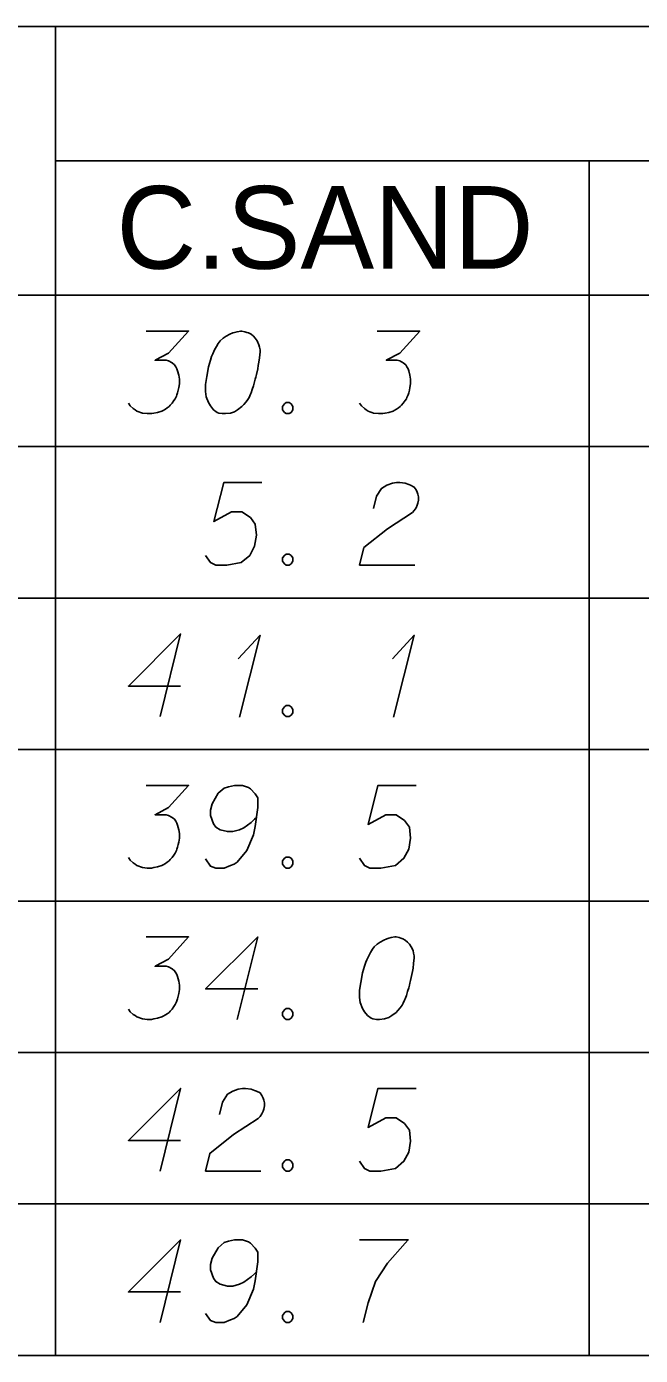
# Model space of a CAD drawing. Extents: x 2074207 to 2076812, y 516372 to 523312.
# Drawn here: x 2076524.4 to 2076560.1, y 517302 to 517379.2 of the extents above; entities that cross this region are included whole.
import ezdxf

# ---------------------------------------------------------------- set-up
doc = ezdxf.new("R2010")
doc.units = 0
for name, color, linetype in [('Prop DirtTable_ Soil Test Results - Outline (Major)', 7, 'Continuous'), ('Prop DirtTable_ Soil Test Results - Outline (Minor)', 7, 'Continuous'), ('Prop DirtTable_ Soil Test Results - Tx (Header - Small)', 7, 'Continuous'), ('Prop DirtTable_ Soil Test Results - Tx (Sample Data)', 7, 'Continuous')]:
    doc.layers.add(name, color=color, linetype=linetype)

msp = doc.modelspace()

# ---------------------------------------------------------------- linework, layer by layer
at = {"layer": 'Prop DirtTable_ Soil Test Results - Outline (Major)'}
for p, q in [((2076260.609, 517363.585), (2076811.903, 517363.585)), ((2076260.609, 517363.585), (2076811.903, 517363.585)), ((2076260.609, 517301.985), (2076811.903, 517301.985))]:
    msp.add_line(p, q, dxfattribs=at)
at = {"layer": 'Prop DirtTable_ Soil Test Results - Outline (Minor)'}
for p, q in [((2076260.609, 517379.185), (2076811.903, 517379.185)), ((2076526.074, 517379.185), (2076526.074, 517354.785)), ((2076526.074, 517371.385), (2076731.93, 517371.385)), ((2076557.094, 517371.385), (2076557.094, 517354.785)), ((2076260.609, 517354.785), (2076811.903, 517354.785)), ((2076260.609, 517354.785), (2076811.903, 517354.785)), ((2076526.074, 517354.785), (2076526.074, 517345.985)), ((2076557.094, 517354.785), (2076557.094, 517345.985)), ((2076260.609, 517345.985), (2076811.903, 517345.985)), ((2076260.609, 517345.985), (2076811.903, 517345.985)), ((2076526.074, 517345.985), (2076526.074, 517337.185)), ((2076557.094, 517345.985), (2076557.094, 517337.185)), ((2076260.609, 517337.185), (2076811.903, 517337.185)), ((2076260.609, 517337.185), (2076811.903, 517337.185)), ((2076526.074, 517337.185), (2076526.074, 517328.385)), ((2076557.094, 517337.185), (2076557.094, 517328.385)), ((2076260.609, 517328.385), (2076811.903, 517328.385)), ((2076260.609, 517328.385), (2076811.903, 517328.385)), ((2076526.074, 517328.385), (2076526.074, 517319.585)), ((2076557.094, 517328.385), (2076557.094, 517319.585)), ((2076260.609, 517319.585), (2076811.903, 517319.585)), ((2076260.609, 517319.585), (2076811.903, 517319.585)), ((2076526.074, 517319.585), (2076526.074, 517310.785)), ((2076557.094, 517319.585), (2076557.094, 517310.785)), ((2076260.609, 517310.785), (2076811.903, 517310.785)), ((2076260.609, 517310.785), (2076811.903, 517310.785)), ((2076526.074, 517310.785), (2076526.074, 517301.985)), ((2076557.094, 517310.785), (2076557.094, 517301.985)), ((2076260.609, 517301.985), (2076811.903, 517301.985))]:
    msp.add_line(p, q, dxfattribs=at)
at = {"layer": 'Prop DirtTable_ Soil Test Results - Tx (Sample Data)'}
for points in [[(2076531.339, 517361.498), (2076533.808, 517361.498), (2076532.644, 517360.213), (2076531.868, 517359.797), (2076532.503, 517359.797), (2076532.644, 517359.759), (2076532.714, 517359.722), (2076532.785, 517359.684), (2076532.855, 517359.646), (2076532.997, 517359.533), (2076533.067, 517359.419), (2076533.138, 517359.306), (2076533.173, 517359.192), (2076533.243, 517358.928), (2076533.279, 517358.701), (2076533.279, 517358.588), (2076533.279, 517358.437), (2076533.243, 517358.21), (2076533.208, 517358.059), (2076533.173, 517357.907), (2076533.138, 517357.794), (2076533.102, 517357.718), (2076533.067, 517357.643), (2076533.032, 517357.567), (2076532.961, 517357.454), (2076532.855, 517357.303), (2076532.75, 517357.189), (2076532.679, 517357.114), (2076532.573, 517357.038), (2076532.467, 517356.963), (2076532.326, 517356.887), (2076532.256, 517356.849), (2076532.009, 517356.774), (2076531.797, 517356.736), (2076531.656, 517356.698), (2076531.409, 517356.698), (2076531.127, 517356.736), (2076531.021, 517356.774), (2076530.915, 517356.811), (2076530.809, 517356.849), (2076530.704, 517356.925), (2076530.598, 517357), (2076530.421, 517357.152), (2076530.316, 517357.303)], [(2076536.912, 517361.498), (2076536.842, 517361.498), (2076536.63, 517361.46), (2076536.489, 517361.422), (2076536.383, 517361.385), (2076536.207, 517361.309), (2076535.995, 517361.196), (2076535.819, 517361.082), (2076535.642, 517360.931), (2076535.536, 517360.78), (2076535.431, 517360.591), (2076535.325, 517360.402), (2076535.219, 517360.175), (2076535.148, 517360.024), (2076535.078, 517359.797), (2076534.972, 517359.419), (2076534.866, 517358.852), (2076534.796, 517358.399), (2076534.796, 517357.983), (2076534.831, 517357.681), (2076534.972, 517357.341), (2076535.078, 517357.152), (2076535.254, 517356.925), (2076535.466, 517356.774), (2076535.572, 517356.736), (2076535.783, 517356.698), (2076535.96, 517356.698), (2076536.242, 517356.736), (2076536.489, 517356.811), (2076536.665, 517356.925), (2076536.912, 517357.114), (2076537.018, 517357.227), (2076537.159, 517357.378), (2076537.265, 517357.529), (2076537.335, 517357.643), (2076537.406, 517357.832), (2076537.441, 517357.907), (2076537.512, 517358.096), (2076537.582, 517358.323), (2076537.653, 517358.55), (2076537.688, 517358.701), (2076537.723, 517358.815), (2076537.759, 517358.966), (2076537.829, 517359.306), (2076537.865, 517359.495), (2076537.9, 517359.684), (2076537.935, 517359.948), (2076537.97, 517360.289), (2076537.97, 517360.402), (2076537.935, 517360.553), (2076537.9, 517360.704), (2076537.794, 517360.931), (2076537.688, 517361.082), (2076537.582, 517361.196), (2076537.441, 517361.309), (2076537.3, 517361.385), (2076537.194, 517361.422), (2076537.089, 517361.46), (2076536.912, 517361.498)], [(2076544.779, 517361.498), (2076547.248, 517361.498), (2076546.084, 517360.213), (2076545.308, 517359.797), (2076545.943, 517359.797), (2076546.084, 517359.759), (2076546.154, 517359.722), (2076546.225, 517359.684), (2076546.295, 517359.646), (2076546.437, 517359.533), (2076546.507, 517359.419), (2076546.578, 517359.306), (2076546.613, 517359.192), (2076546.683, 517358.928), (2076546.719, 517358.701), (2076546.719, 517358.588), (2076546.719, 517358.437), (2076546.683, 517358.21), (2076546.648, 517358.059), (2076546.613, 517357.907), (2076546.578, 517357.794), (2076546.542, 517357.718), (2076546.507, 517357.643), (2076546.472, 517357.567), (2076546.401, 517357.454), (2076546.295, 517357.303), (2076546.19, 517357.189), (2076546.119, 517357.114), (2076546.013, 517357.038), (2076545.907, 517356.963), (2076545.766, 517356.887), (2076545.696, 517356.849), (2076545.449, 517356.774), (2076545.237, 517356.736), (2076545.096, 517356.698), (2076544.849, 517356.698), (2076544.567, 517356.736), (2076544.461, 517356.774), (2076544.355, 517356.811), (2076544.249, 517356.849), (2076544.144, 517356.925), (2076544.038, 517357), (2076543.861, 517357.152), (2076543.756, 517357.303)], [(2076539.487, 517357.341), (2076539.664, 517357.341), (2076539.769, 517357.265), (2076539.875, 517357.114), (2076539.875, 517356.925), (2076539.769, 517356.774), (2076539.664, 517356.698), (2076539.487, 517356.698), (2076539.381, 517356.774), (2076539.276, 517356.925), (2076539.276, 517357.114), (2076539.381, 517357.265), (2076539.487, 517357.341)], [(2076538.076, 517352.698), (2076535.854, 517352.698), (2076535.289, 517350.43), (2076536.312, 517350.997), (2076536.912, 517350.997), (2076537.406, 517350.657), (2076537.688, 517350.279), (2076537.759, 517349.637), (2076537.653, 517348.994), (2076537.371, 517348.465), (2076536.877, 517348.049), (2076536.03, 517347.898), (2076535.395, 517347.898), (2076535.078, 517348.049), (2076534.796, 517348.465)], [(2076544.567, 517351.186), (2076544.743, 517351.904), (2076545.026, 517352.358), (2076545.343, 517352.547), (2076545.66, 517352.66), (2076545.907, 517352.698), (2076546.084, 517352.698), (2076546.401, 517352.66), (2076546.613, 517352.585), (2076546.719, 517352.547), (2076546.93, 517352.433), (2076547.036, 517352.282), (2076547.107, 517352.131), (2076547.142, 517352.018), (2076547.177, 517351.867), (2076547.177, 517351.678), (2076547.142, 517351.489), (2076547.107, 517351.375), (2076547.036, 517351.224), (2076546.93, 517351.073), (2076546.825, 517350.959), (2076545.378, 517350.015), (2076544.003, 517348.918), (2076543.756, 517347.898), (2076546.966, 517347.898)], [(2076539.487, 517348.541), (2076539.664, 517348.541), (2076539.769, 517348.465), (2076539.875, 517348.314), (2076539.875, 517348.125), (2076539.769, 517347.974), (2076539.664, 517347.898), (2076539.487, 517347.898), (2076539.381, 517347.974), (2076539.276, 517348.125), (2076539.276, 517348.314), (2076539.381, 517348.465), (2076539.487, 517348.541)], [(2076533.349, 517340.874), (2076530.316, 517340.874), (2076533.349, 517343.898), (2076532.15, 517339.098)], [(2076536.7, 517342.462), (2076537.97, 517343.822), (2076536.771, 517339.06)], [(2076545.66, 517342.462), (2076546.93, 517343.822), (2076545.731, 517339.06)], [(2076539.487, 517339.741), (2076539.664, 517339.741), (2076539.769, 517339.665), (2076539.875, 517339.514), (2076539.875, 517339.325), (2076539.769, 517339.174), (2076539.664, 517339.098), (2076539.487, 517339.098), (2076539.381, 517339.174), (2076539.276, 517339.325), (2076539.276, 517339.514), (2076539.381, 517339.665), (2076539.487, 517339.741)], [(2076531.339, 517335.098), (2076533.808, 517335.098), (2076532.644, 517333.813), (2076531.868, 517333.397), (2076532.503, 517333.397), (2076532.644, 517333.359), (2076532.714, 517333.322), (2076532.785, 517333.284), (2076532.855, 517333.246), (2076532.997, 517333.133), (2076533.067, 517333.019), (2076533.138, 517332.906), (2076533.173, 517332.792), (2076533.243, 517332.528), (2076533.279, 517332.301), (2076533.279, 517332.188), (2076533.279, 517332.037), (2076533.243, 517331.81), (2076533.208, 517331.659), (2076533.173, 517331.507), (2076533.138, 517331.394), (2076533.102, 517331.318), (2076533.067, 517331.243), (2076533.032, 517331.167), (2076532.961, 517331.054), (2076532.855, 517330.903), (2076532.75, 517330.789), (2076532.679, 517330.714), (2076532.573, 517330.638), (2076532.467, 517330.563), (2076532.326, 517330.487), (2076532.256, 517330.449), (2076532.009, 517330.374), (2076531.797, 517330.336), (2076531.656, 517330.298), (2076531.409, 517330.298), (2076531.127, 517330.336), (2076531.021, 517330.374), (2076530.915, 517330.411), (2076530.809, 517330.449), (2076530.704, 517330.525), (2076530.598, 517330.6), (2076530.421, 517330.752), (2076530.316, 517330.903)], [(2076534.796, 517330.827), (2076535.078, 517330.411), (2076535.395, 517330.298), (2076535.889, 517330.298), (2076536.242, 517330.449), (2076536.454, 517330.525), (2076536.63, 517330.638), (2076537.194, 517331.318), (2076537.582, 517332.226), (2076537.688, 517332.717), (2076537.829, 517333.813), (2076537.829, 517334.38), (2076537.688, 517334.607), (2076537.406, 517334.909), (2076537.3, 517334.985), (2076536.947, 517335.098), (2076536.489, 517335.098), (2076536.136, 517335.022), (2076535.889, 517334.947), (2076535.536, 517334.644), (2076535.184, 517334.04), (2076535.078, 517333.662), (2076535.078, 517333.359), (2076535.254, 517332.868), (2076535.395, 517332.679), (2076535.642, 517332.528), (2076536.066, 517332.415), (2076536.383, 517332.415), (2076536.771, 517332.528), (2076537.018, 517332.641), (2076537.441, 517332.944), (2076537.653, 517333.133), (2076537.759, 517333.246)], [(2076547.036, 517335.098), (2076544.814, 517335.098), (2076544.249, 517332.83), (2076545.272, 517333.397), (2076545.872, 517333.397), (2076546.366, 517333.057), (2076546.648, 517332.679), (2076546.719, 517332.037), (2076546.613, 517331.394), (2076546.331, 517330.865), (2076545.837, 517330.449), (2076544.99, 517330.298), (2076544.355, 517330.298), (2076544.038, 517330.449), (2076543.756, 517330.865)], [(2076539.487, 517330.941), (2076539.664, 517330.941), (2076539.769, 517330.865), (2076539.875, 517330.714), (2076539.875, 517330.525), (2076539.769, 517330.374), (2076539.664, 517330.298), (2076539.487, 517330.298), (2076539.381, 517330.374), (2076539.276, 517330.525), (2076539.276, 517330.714), (2076539.381, 517330.865), (2076539.487, 517330.941)], [(2076531.339, 517326.298), (2076533.808, 517326.298), (2076532.644, 517325.013), (2076531.868, 517324.597), (2076532.503, 517324.597), (2076532.644, 517324.559), (2076532.714, 517324.522), (2076532.785, 517324.484), (2076532.855, 517324.446), (2076532.997, 517324.333), (2076533.067, 517324.219), (2076533.138, 517324.106), (2076533.173, 517323.992), (2076533.243, 517323.728), (2076533.279, 517323.501), (2076533.279, 517323.388), (2076533.279, 517323.237), (2076533.243, 517323.01), (2076533.208, 517322.859), (2076533.173, 517322.707), (2076533.138, 517322.594), (2076533.102, 517322.518), (2076533.067, 517322.443), (2076533.032, 517322.367), (2076532.961, 517322.254), (2076532.855, 517322.103), (2076532.75, 517321.989), (2076532.679, 517321.914), (2076532.573, 517321.838), (2076532.467, 517321.763), (2076532.326, 517321.687), (2076532.256, 517321.649), (2076532.009, 517321.574), (2076531.797, 517321.536), (2076531.656, 517321.498), (2076531.409, 517321.498), (2076531.127, 517321.536), (2076531.021, 517321.574), (2076530.915, 517321.611), (2076530.809, 517321.649), (2076530.704, 517321.725), (2076530.598, 517321.8), (2076530.421, 517321.952), (2076530.316, 517322.103)], [(2076537.829, 517323.274), (2076534.796, 517323.274), (2076537.829, 517326.298), (2076536.63, 517321.498)], [(2076545.872, 517326.298), (2076545.802, 517326.298), (2076545.59, 517326.26), (2076545.449, 517326.222), (2076545.343, 517326.185), (2076545.167, 517326.109), (2076544.955, 517325.996), (2076544.779, 517325.882), (2076544.602, 517325.731), (2076544.496, 517325.58), (2076544.391, 517325.391), (2076544.285, 517325.202), (2076544.179, 517324.975), (2076544.108, 517324.824), (2076544.038, 517324.597), (2076543.932, 517324.219), (2076543.826, 517323.652), (2076543.756, 517323.199), (2076543.756, 517322.783), (2076543.791, 517322.481), (2076543.932, 517322.141), (2076544.038, 517321.952), (2076544.214, 517321.725), (2076544.426, 517321.574), (2076544.532, 517321.536), (2076544.743, 517321.498), (2076544.92, 517321.498), (2076545.202, 517321.536), (2076545.449, 517321.611), (2076545.625, 517321.725), (2076545.872, 517321.914), (2076545.978, 517322.027), (2076546.119, 517322.178), (2076546.225, 517322.329), (2076546.295, 517322.443), (2076546.366, 517322.632), (2076546.401, 517322.707), (2076546.472, 517322.896), (2076546.542, 517323.123), (2076546.613, 517323.35), (2076546.648, 517323.501), (2076546.683, 517323.615), (2076546.719, 517323.766), (2076546.789, 517324.106), (2076546.825, 517324.295), (2076546.86, 517324.484), (2076546.895, 517324.748), (2076546.93, 517325.089), (2076546.93, 517325.202), (2076546.895, 517325.353), (2076546.86, 517325.504), (2076546.754, 517325.731), (2076546.648, 517325.882), (2076546.542, 517325.996), (2076546.401, 517326.109), (2076546.26, 517326.185), (2076546.154, 517326.222), (2076546.049, 517326.26), (2076545.872, 517326.298)], [(2076539.487, 517322.141), (2076539.664, 517322.141), (2076539.769, 517322.065), (2076539.875, 517321.914), (2076539.875, 517321.725), (2076539.769, 517321.574), (2076539.664, 517321.498), (2076539.487, 517321.498), (2076539.381, 517321.574), (2076539.276, 517321.725), (2076539.276, 517321.914), (2076539.381, 517322.065), (2076539.487, 517322.141)], [(2076533.349, 517314.474), (2076530.316, 517314.474), (2076533.349, 517317.498), (2076532.15, 517312.698)], [(2076535.607, 517315.986), (2076535.783, 517316.704), (2076536.066, 517317.158), (2076536.383, 517317.347), (2076536.7, 517317.46), (2076536.947, 517317.498), (2076537.124, 517317.498), (2076537.441, 517317.46), (2076537.653, 517317.385), (2076537.759, 517317.347), (2076537.97, 517317.233), (2076538.076, 517317.082), (2076538.147, 517316.931), (2076538.182, 517316.818), (2076538.217, 517316.667), (2076538.217, 517316.478), (2076538.182, 517316.289), (2076538.147, 517316.175), (2076538.076, 517316.024), (2076537.97, 517315.873), (2076537.865, 517315.759), (2076536.418, 517314.815), (2076535.043, 517313.718), (2076534.796, 517312.698), (2076538.006, 517312.698)], [(2076547.036, 517317.498), (2076544.814, 517317.498), (2076544.249, 517315.23), (2076545.272, 517315.797), (2076545.872, 517315.797), (2076546.366, 517315.457), (2076546.648, 517315.079), (2076546.719, 517314.437), (2076546.613, 517313.794), (2076546.331, 517313.265), (2076545.837, 517312.849), (2076544.99, 517312.698), (2076544.355, 517312.698), (2076544.038, 517312.849), (2076543.756, 517313.265)], [(2076539.487, 517313.341), (2076539.664, 517313.341), (2076539.769, 517313.265), (2076539.875, 517313.114), (2076539.875, 517312.925), (2076539.769, 517312.774), (2076539.664, 517312.698), (2076539.487, 517312.698), (2076539.381, 517312.774), (2076539.276, 517312.925), (2076539.276, 517313.114), (2076539.381, 517313.265), (2076539.487, 517313.341)], [(2076533.349, 517305.674), (2076530.316, 517305.674), (2076533.349, 517308.698), (2076532.15, 517303.898)], [(2076534.796, 517304.427), (2076535.078, 517304.011), (2076535.395, 517303.898), (2076535.889, 517303.898), (2076536.242, 517304.049), (2076536.454, 517304.125), (2076536.63, 517304.238), (2076537.194, 517304.918), (2076537.582, 517305.826), (2076537.688, 517306.317), (2076537.829, 517307.413), (2076537.829, 517307.98), (2076537.688, 517308.207), (2076537.406, 517308.509), (2076537.3, 517308.585), (2076536.947, 517308.698), (2076536.489, 517308.698), (2076536.136, 517308.622), (2076535.889, 517308.547), (2076535.536, 517308.244), (2076535.184, 517307.64), (2076535.078, 517307.262), (2076535.078, 517306.959), (2076535.254, 517306.468), (2076535.395, 517306.279), (2076535.642, 517306.128), (2076536.066, 517306.015), (2076536.383, 517306.015), (2076536.771, 517306.128), (2076537.018, 517306.241), (2076537.441, 517306.544), (2076537.653, 517306.733), (2076537.759, 517306.846)], [(2076543.756, 517308.698), (2076546.578, 517308.698), (2076546.401, 517308.509), (2076545.378, 517307.337), (2076544.673, 517306.279), (2076544.249, 517305.032), (2076543.967, 517303.898)], [(2076539.487, 517304.541), (2076539.664, 517304.541), (2076539.769, 517304.465), (2076539.875, 517304.314), (2076539.875, 517304.125), (2076539.769, 517303.974), (2076539.664, 517303.898), (2076539.487, 517303.898), (2076539.381, 517303.974), (2076539.276, 517304.125), (2076539.276, 517304.314), (2076539.381, 517304.465), (2076539.487, 517304.541)]]:
    msp.add_lwpolyline(points, dxfattribs=at)

# ---------------------------------------------------------------- texts
at = {"layer": 'Prop DirtTable_ Soil Test Results - Tx (Header - Small)'}
msp.add_text('C.SAND', height=4.8, dxfattribs=at).set_placement((2076529.618, 517365.121))

doc.saveas('drawing.dxf')
